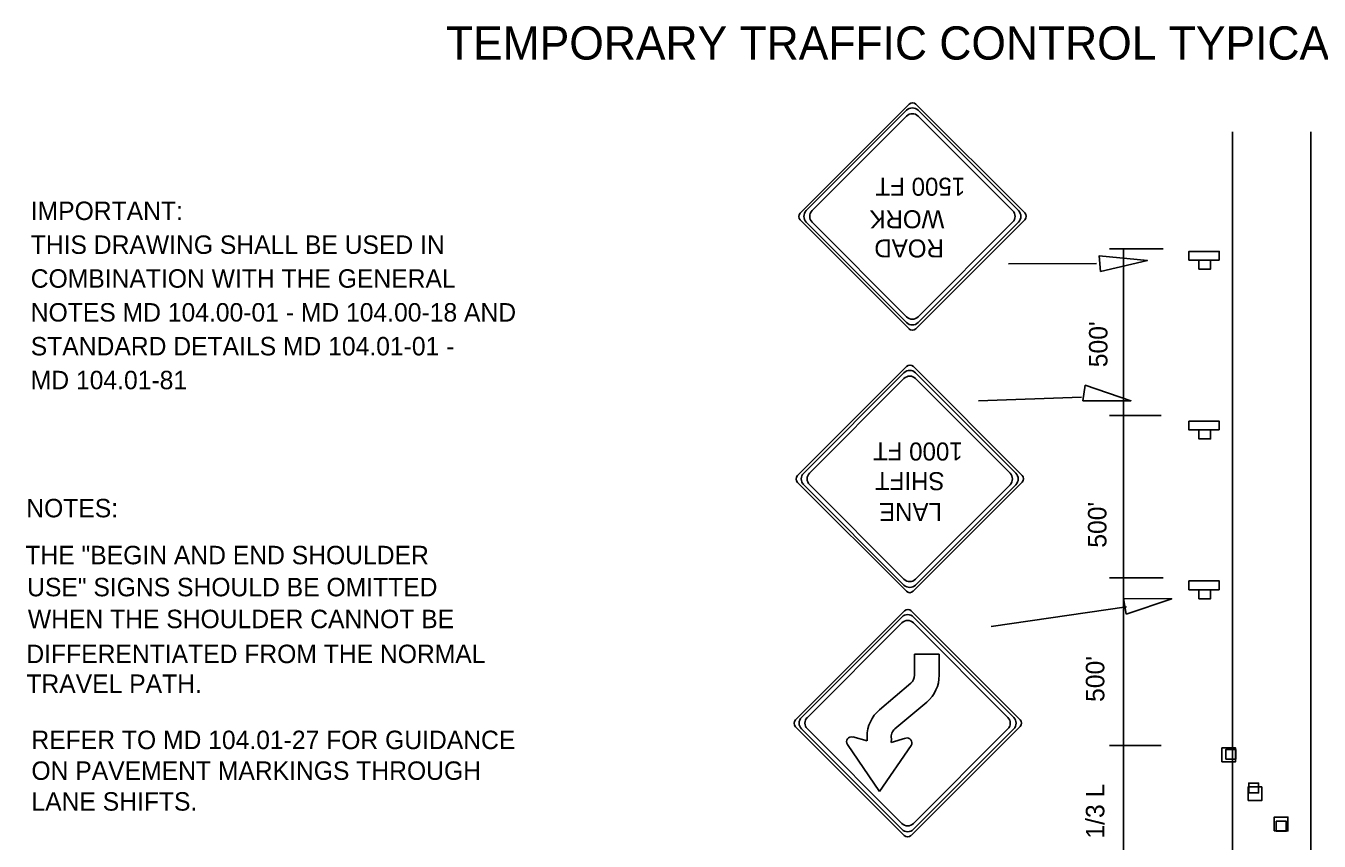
# Model space of a CAD drawing. Extents: x 1531.38 to 1538.58, y 1529.59 to 1539.28.
# Drawn here: x 1531.376 to 1535.582, y 1536.629 to 1539.279 of the extents above; entities that cross this region are included whole.
import ezdxf

# ---------------------------------------------------------------- set-up
doc = ezdxf.new("R2010")
doc.units = 0
for name, color, linetype in [('DETL-DIMS', 7, 'Continuous'), ('DETL-LINE', 7, 'Continuous'), ('DETL-NOTE', 7, 'Continuous'), ('DETL-TITL', 7, 'Continuous'), ('USER-BORD', 7, 'Continuous')]:
    doc.layers.add(name, color=color, linetype=linetype)

# ---------------------------------------------------------------- blocks, each defined once
blk = doc.blocks.new('CD20')
at = {"layer": 'USER-BORD'}
blk.add_lwpolyline([(-0.0625, -0.0625), (0, -0.0625), (0, 0), (-0.0625, 0)], close=True, dxfattribs=at)
blk = doc.blocks.new('SIGN13')
at = {"layer": 'USER-BORD'}
for points in [[(-0.0134, 0.0182), (0.011, 0.0189), (0.011, 0.0371), (-0.0134, 0.0371)], [(-0.0314, 0.0182), (-0.0314, 0), (0.032, 0), (0.032, 0.0182)]]:
    blk.add_lwpolyline(points, close=True, dxfattribs=at)

msp = doc.modelspace()

# ---------------------------------------------------------------- linework, layer by layer
at = {"layer": 'DETL-DIMS'}
for p, q in [((1534.901, 1538.5537), (1535.0756, 1538.5537)), ((1534.9463, 1538.5537), (1534.9463, 1535.5589)), ((1534.8579, 1538.5061), (1534.5721, 1538.5052)), ((1534.8092, 1538.0722), (1534.4744, 1538.0603)), ((1534.901, 1538.0124), (1535.0689, 1538.0124)), ((1534.901, 1537.485), (1535.0756, 1537.485)), ((1534.9557, 1537.39), (1534.5152, 1537.3269)), ((1534.901, 1536.9391), (1535.0689, 1536.9391))]:
    msp.add_line(p, q, dxfattribs=at)
for points in [[(1534.8709, 1538.4802), (1534.8673, 1538.5317), (1535.0237, 1538.5165)], [(1534.8133, 1538.0595), (1534.8217, 1538.1105), (1534.9705, 1538.06)], [(1534.9543, 1537.3661), (1534.9459, 1537.417), (1535.103, 1537.4168)]]:
    msp.add_lwpolyline(points, close=True, dxfattribs=at)
at = {"layer": 'DETL-LINE'}
for p, q in [((1534.2492, 1539.0245), (1533.8945, 1538.6698)), ((1533.9145, 1538.6781), (1534.2406, 1539.0043)), ((1534.6251, 1538.6706), (1534.2712, 1539.0245)), ((1534.2783, 1539.0043), (1534.6044, 1538.6781)), ((1534.2406, 1538.9855), (1533.9333, 1538.6781)), ((1534.5856, 1538.6781), (1534.2783, 1538.9855)), ((1535.3002, 1538.9346), (1535.3002, 1531.7918)), ((1535.5552, 1538.9346), (1535.5552, 1531.7918)), ((1534.5856, 1538.6781), (1534.5856, 1538.6781)), ((1533.8945, 1538.6479), (1534.2485, 1538.2939)), ((1534.2406, 1538.3143), (1533.9145, 1538.6405)), ((1533.9333, 1538.6405), (1534.2406, 1538.3331)), ((1534.2704, 1538.2939), (1534.6251, 1538.6486)), ((1534.6044, 1538.6405), (1534.2783, 1538.3143)), ((1534.2783, 1538.3331), (1534.5856, 1538.6405)), ((1534.2408, 1538.1714), (1533.8861, 1537.8167)), ((1534.6167, 1537.8175), (1534.2627, 1538.1714)), ((1533.906, 1537.825), (1534.2321, 1538.1512)), ((1534.2321, 1538.1324), (1533.9249, 1537.825)), ((1534.5772, 1537.825), (1534.2698, 1538.1324)), ((1534.2699, 1538.1512), (1534.596, 1537.825)), ((1534.5772, 1537.825), (1534.5772, 1537.825)), ((1533.8861, 1537.7947), (1534.24, 1537.4408)), ((1534.2321, 1537.4612), (1533.906, 1537.7873)), ((1533.9249, 1537.7874), (1534.2321, 1537.48)), ((1534.262, 1537.4408), (1534.6167, 1537.7955)), ((1534.596, 1537.7873), (1534.2699, 1537.4612)), ((1534.2699, 1537.48), (1534.5772, 1537.7873)), ((1534.2338, 1537.3774), (1533.8791, 1537.0227)), ((1534.6097, 1537.0235), (1534.2557, 1537.3774)), ((1533.899, 1537.031), (1534.2251, 1537.3572)), ((1534.2251, 1537.3384), (1533.9179, 1537.031)), ((1534.5702, 1537.031), (1534.2628, 1537.3384)), ((1534.2629, 1537.3572), (1534.589, 1537.031)), ((1534.3468, 1537.2365), (1534.2667, 1537.2368)), ((1534.2667, 1537.2368), (1534.2667, 1537.1681)), ((1534.3467, 1537.1681), (1534.3468, 1537.2365)), ((1534.2546, 1537.1421), (1534.1527, 1537.0558)), ((1534.2027, 1536.9942), (1534.3062, 1537.0808)), ((1534.5702, 1537.031), (1534.5702, 1537.031)), ((1533.8791, 1537.0007), (1534.233, 1536.6468)), ((1534.2251, 1536.6672), (1533.899, 1536.9933)), ((1533.9179, 1536.9934), (1534.2251, 1536.686)), ((1534.255, 1536.6468), (1534.6097, 1537.0015)), ((1534.589, 1536.9933), (1534.2629, 1536.6672)), ((1534.2629, 1536.686), (1534.5702, 1536.9933)), ((1534.0483, 1536.9432), (1534.1525, 1536.7898)), ((1534.1121, 1536.9542), (1534.0656, 1536.9672)), ((1534.1121, 1536.9685), (1534.1121, 1536.9542)), ((1534.1525, 1536.7898), (1534.2551, 1536.94)), ((1534.2376, 1536.9639), (1534.1907, 1536.9497)), ((1534.1907, 1536.9497), (1534.1912, 1536.9616))]:
    msp.add_line(p, q, dxfattribs=at)
for points in [[(1535.2661, 1536.8868), (1535.3109, 1536.8868), (1535.3109, 1536.9316), (1535.2661, 1536.9316)], [(1535.3511, 1536.7603), (1535.3959, 1536.7603), (1535.3959, 1536.8051), (1535.3511, 1536.8051)], [(1535.4362, 1536.6621), (1535.481, 1536.6621), (1535.481, 1536.7069), (1535.4362, 1536.7069)]]:
    msp.add_lwpolyline(points, close=True, dxfattribs=at)
for centre, radius, start, end in [((1534.2594, 1538.9855), 0.0266, 45, 135), ((1534.2602, 1539.0135), 0.0155, 45, 135), ((1534.2594, 1538.9666), 0.0266, 45, 135), ((1533.9055, 1538.6588), 0.0155, 135, 225), ((1533.9333, 1538.6593), 0.0266, 135, 225), ((1533.9521, 1538.6593), 0.0266, 135, 225), ((1534.5668, 1538.6593), 0.0266, 315, 45), ((1534.5856, 1538.6593), 0.0266, 315, 45), ((1534.6142, 1538.6596), 0.0155, 315, 45), ((1534.2594, 1538.3519), 0.0266, 225, 315), ((1534.2594, 1538.3331), 0.0266, 225, 315), ((1534.2594, 1538.3049), 0.0155, 225, 315), ((1534.2518, 1538.1604), 0.0155, 45, 135), ((1534.251, 1538.1135), 0.0266, 45, 135), ((1534.251, 1538.1323), 0.0266, 45, 135), ((1533.9248, 1537.8062), 0.0266, 135, 225), ((1533.9436, 1537.8062), 0.0266, 135, 225), ((1534.5583, 1537.8061), 0.0266, 315, 45), ((1534.5772, 1537.8061), 0.0266, 315, 45), ((1533.8971, 1537.8057), 0.0155, 135, 225), ((1534.6057, 1537.8065), 0.0155, 315, 45), ((1534.251, 1537.4988), 0.0266, 225, 315), ((1534.251, 1537.48), 0.0266, 225, 315), ((1534.251, 1537.4518), 0.0155, 225, 315), ((1534.244, 1537.3383), 0.0266, 45, 135), ((1534.2448, 1537.3664), 0.0155, 45, 135), ((1534.244, 1537.3195), 0.0266, 45, 135), ((1534.2323, 1537.1682), 0.0343, 310.2409, 359.906), ((1534.2323, 1537.1682), 0.1144, 310.2409, 359.906), ((1533.9178, 1537.0122), 0.0266, 135, 225), ((1533.9366, 1537.0122), 0.0266, 135, 225), ((1534.2266, 1536.9684), 0.1144, 130.2409, 179.906), ((1534.5513, 1537.0121), 0.0266, 315, 45), ((1534.5702, 1537.0121), 0.0266, 315, 45), ((1534.5987, 1537.0125), 0.0155, 315, 45), ((1533.8901, 1537.0117), 0.0155, 135, 225), ((1534.2249, 1536.968), 0.0343, 130.2409, 190.6511), ((1534.0614, 1536.952), 0.0157, 74.4164, 214.1663), ((1534.2422, 1536.9488), 0.0157, 325.6457, 106.8036), ((1534.244, 1536.7048), 0.0266, 225, 315), ((1534.244, 1536.686), 0.0266, 225, 315), ((1534.244, 1536.6578), 0.0155, 225, 315)]:
    msp.add_arc(centre, radius, start, end, dxfattribs=at)

# ---------------------------------------------------------------- block references
at = {"layer": 'DETL-LINE', "xscale": 1.550372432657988, "yscale": 1.550372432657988, "rotation": 180}
for p in [(1535.2087, 1538.5455), (1535.2087, 1537.9936), (1535.2087, 1537.4743)]:
    msp.add_blockref('SIGN13', p, dxfattribs=at)
at = {"layer": 'DETL-LINE', "xscale": 0.5153677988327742, "yscale": 0.5153677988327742}
for p in [(1535.3112, 1536.9269), (1535.3112, 1536.9269), (1535.3857, 1536.8176), (1535.3857, 1536.8176), (1535.4753, 1536.6932), (1535.4753, 1536.6932)]:
    msp.add_blockref('CD20', p, dxfattribs=at)

# ---------------------------------------------------------------- texts
at = {"layer": 'DETL-LINE'}
for s, p in [('1500 FT', (1534.4311, 1538.7851)), ('WORK', (1534.3633, 1538.6794)), ('ROAD', (1534.3619, 1538.5844)), ('1000 FT', (1534.4231, 1537.9245)), ('SHIFT', (1534.364, 1537.8281)), ('LANE', (1534.3555, 1537.7278))]:
    msp.add_text(s, height=0.05854, rotation=180, dxfattribs=at).set_placement(p)
at = {"layer": 'DETL-NOTE'}
for s, p in [('IMPORTANT:', (1531.392, 1538.6475)), ('THIS DRAWING SHALL BE USED IN', (1531.392, 1538.5375)), ('COMBINATION WITH THE GENERAL', (1531.392, 1538.4275)), ('NOTES MD 104.00-01 - MD 104.00-18 AND', (1531.392, 1538.3175)), ('STANDARD DETAILS MD 104.01-01 -', (1531.392, 1538.2075)), ('MD 104.01-81', (1531.392, 1538.0975)), ('NOTES:', (1531.3774, 1537.6812)), ('THE "BEGIN AND END SHOULDER', (1531.3743, 1537.5286)), ('USE" SIGNS SHOULD BE OMITTED', (1531.3801, 1537.4245)), ('WHEN THE SHOULDER CANNOT BE', (1531.3826, 1537.3209)), ('DIFFERENTIATED FROM THE NORMAL', (1531.3777, 1537.2073)), ('TRAVEL PATH.', (1531.3777, 1537.1104)), ('REFER TO MD 104.01-27 FOR GUIDANCE ', (1531.3942, 1536.9278)), ('ON PAVEMENT MARKINGS THROUGH ', (1531.3942, 1536.8278)), ('LANE SHIFTS.', (1531.3942, 1536.7278))]:
    msp.add_text(s, height=0.06, dxfattribs=at).set_placement(p)
for s, p in [("500'", (1534.8939, 1538.169)), ("500'", (1534.8906, 1537.5824)), ("500'", (1534.8838, 1537.0812)), ('1/3 L', (1534.8838, 1536.6369))]:
    msp.add_text(s, height=0.06, rotation=90, dxfattribs=at).set_placement(p)
at = {"layer": 'DETL-TITL'}
msp.add_text('TEMPORARY TRAFFIC CONTROL TYPICAL APPLICATION', height=0.108, dxfattribs=at).set_placement((1532.7424, 1539.169))

doc.saveas('drawing.dxf')
